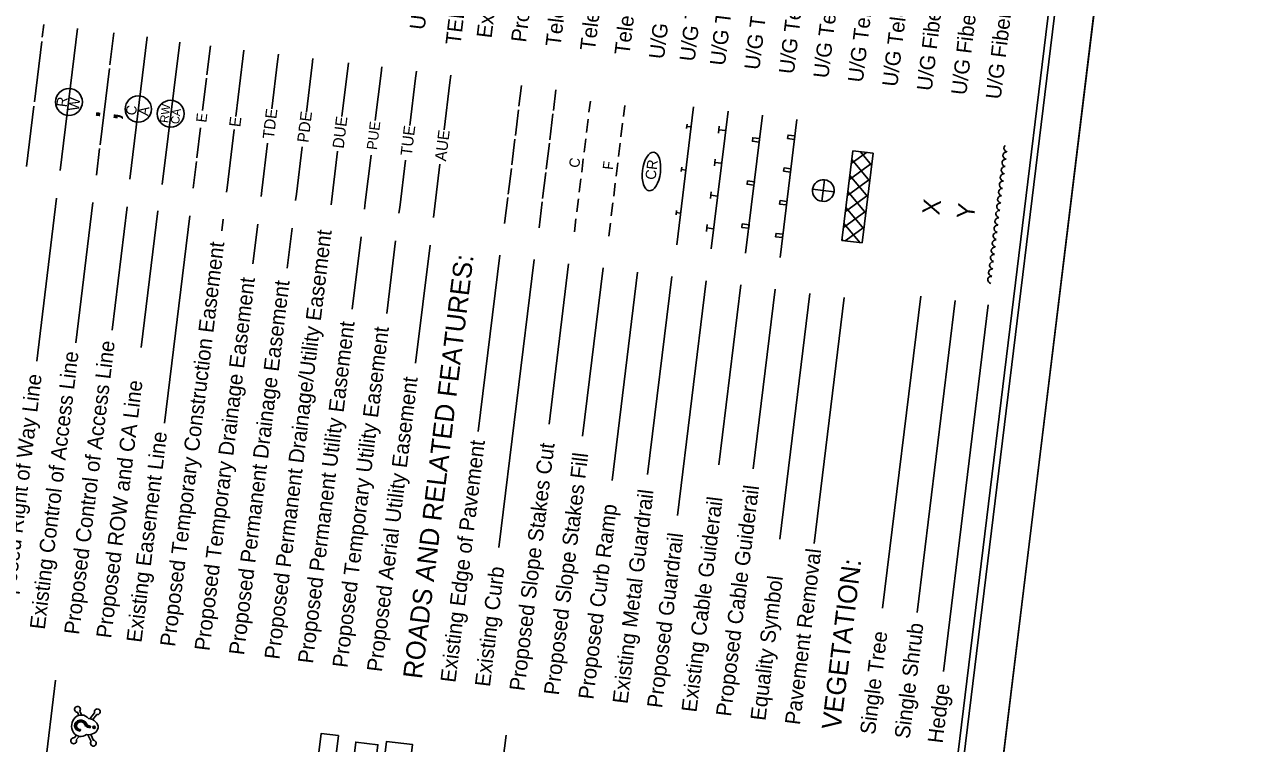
# Model space of a CAD drawing. Extents: x 480781 to 482077, y 490810 to 492615.
# Drawn here: x 481377 to 482077, y 491374 to 491789 of the extents above; entities that cross this region are included whole.
import ezdxf

# ---------------------------------------------------------------- set-up
doc = ezdxf.new("R2010")
doc.units = 0
for name, color, linetype in [('Prop Easement Permanent Drainage Utility', 7, 'Continuous'), ('Prop WCC CELL', 7, 'Continuous'), ('Prop XS SS Elevation Text', 7, 'Continuous'), ('Sheet Cutting Line CELL', 7, 'Continuous'), ('Sheet Plot Border Inside CELL', 7, 'Continuous'), ('Sheet Plot Border Outside CELL', 7, 'Continuous'), ('Sheet Symbology CELL', 7, 'Continuous')]:
    doc.layers.add(name, color=color, linetype=linetype)

msp = doc.modelspace()

# ---------------------------------------------------------------- linework, layer by layer
at = {"layer": 'Prop Easement Permanent Drainage Utility'}
for p, q in [((481559.54, 491735.39), (481563.32, 491766.36)), ((481553.32, 491684.47), (481557.11, 491715.54))]:
    msp.add_line(p, q, dxfattribs=at)
at = {"layer": 'Prop WCC CELL'}
msp.add_ellipse((481737.84, 491703.74), major_axis=(1.36, 11.13), ratio=0.462467, dxfattribs=at)
at = {"layer": 'Prop XS SS Elevation Text'}
for p, q in [((481407.22, 491392.23), (481408.08, 491390.42)), ((481408.63, 491392.89), (481409.69, 491390.65)), ((481414.43, 491388.5), (481417.15, 491391.85)), ((481415.99, 491387.95), (481418.36, 491390.87)), ((481408.84, 491381.28), (481408.96, 491382.26)), ((481411.38, 491384.2), (481411.38, 491384.2)), ((481413.82, 491383.41), (481414.68, 491383.3)), ((481413.83, 491383.55), (481414.7, 491383.44)), ((481413.85, 491383.69), (481414.72, 491383.58)), ((481413.87, 491383.83), (481414.73, 491383.72)), ((481413.88, 491383.97), (481414.75, 491383.86)), ((481413.9, 491384.11), (481414.77, 491384.01)), ((481413.92, 491384.25), (481414.78, 491384.15)), ((481413.94, 491384.39), (481414.8, 491384.29)), ((481414.68, 491383.3), (481414.8, 491384.29)), ((481405.41, 491377.41), (481406.68, 491378.97)), ((481406.62, 491376.43), (481408.19, 491378.35)), ((481413.3, 491379.3), (481415.14, 491375.39)), ((481414.95, 491379.46), (481416.55, 491376.05))]:
    msp.add_line(p, q, dxfattribs=at)
for radius in [0.709, 0.551, 0.391, 0.233, 0.0755]:
    msp.add_circle((481416.88, 491383.57), radius, dxfattribs=at)
for centre, start, end in [((481407.31, 491393.89), 323.23034, 267.1389), ((481418.68, 491392.5), 258.93413, 202.84268), ((481405.1, 491375.79), 78.93413, 22.84268), ((481416.47, 491374.4), 143.23034, 87.1389)]:
    msp.add_arc(centre, 1.66, start, end, dxfattribs=at)
for centre, major_axis, ratio, start_param, end_param in [((481409.43, 491384.44), (0.75, 6.18), 0.885014, 5.564242, 10.143721), ((481412.97, 491384.01), (6.18, -0.75), 0.752542, 4.722735, 7.843636), ((481409.23, 491384.47), (-3.54, 0.43), 0.9, 3.567618, 7.853982), ((481409.23, 491384.47), (-3.39, 0.41), 0.9, 3.567618, 7.853982), ((481409.23, 491384.47), (-3.23, 0.39), 0.9, 3.567618, 7.853982), ((481409.23, 491384.47), (-3.07, 0.38), 0.9, 3.567618, 7.853982), ((481409.23, 491384.47), (-2.92, 0.36), 0.9, 3.567618, 7.853982), ((481409.23, 491384.47), (-2.76, 0.34), 0.9, 3.567618, 7.853982), ((481409.23, 491384.47), (-2.61, 0.32), 0.9, 3.567618, 7.853982), ((481409.23, 491384.47), (-2.45, 0.3), 0.9, 3.567618, 7.853982), ((481414.11, 491385.8), (-2.66, 0.32), 0.9, 0.426026, 1.570796), ((481414.11, 491385.8), (-2.5, 0.31), 0.9, 0.426026, 1.570796), ((481414.11, 491385.8), (-2.35, 0.29), 0.9, 0.426026, 1.570796), ((481414.11, 491385.8), (-2.19, 0.27), 0.9, 0.426026, 1.570796), ((481414.11, 491385.8), (-2.03, 0.25), 0.9, 0.426026, 1.570796), ((481414.11, 491385.8), (-1.88, 0.23), 0.9, 0.426026, 1.570796), ((481414.11, 491385.8), (-1.72, 0.21), 0.9, 0.426026, 1.570796), ((481414.11, 491385.8), (-1.56, 0.19), 0.9, 0.426026, 1.570796)]:
    msp.add_ellipse(centre, major_axis=major_axis, ratio=ratio, start_param=start_param, end_param=end_param, dxfattribs=at)
at = {"layer": 'Sheet Cutting Line CELL'}
msp.add_line((481872.48, 490810.45), (482076.64, 492482.02), dxfattribs=at)
at = {"layer": 'Sheet Plot Border Inside CELL'}
msp.add_lwpolyline([(481851.77, 490826.07), (482053.81, 492480.28), (481006.5, 492608.2), (480804.45, 490953.99)], close=True, dxfattribs=at)
at = {"layer": 'Sheet Plot Border Outside CELL'}
msp.add_lwpolyline([(481872.48, 490810.45), (482076.64, 492482.02), (480984.76, 492615.38), (480780.59, 490943.81)], close=True, dxfattribs=at)
at = {"layer": 'Sheet Symbology CELL'}
for p, q in [((481387.03, 491781.08), (481387.94, 491788.52)), ((481397.34, 491704.26), (481407.34, 491786.15)), ((481425.93, 491765.12), (481428.19, 491783.61)), ((481437.48, 491699.36), (481447.48, 491781.25)), ((481382.48, 491743.86), (481386.73, 491778.6)), ((481456.16, 491696.35), (481466.16, 491778.24)), ((481481.85, 491759.45), (481483.88, 491776.07)), ((481502.59, 491768.86), (481503.19, 491773.71)), ((481498.5, 491735.35), (481502.59, 491768.86)), ((481519.2, 491739.87), (481522.54, 491767.16)), ((481522.54, 491767.16), (481523.04, 491771.28)), ((481542.44, 491765.18), (481542.89, 491768.86)), ((481420.3, 491719.05), (481425.69, 491763.14)), ((481539.11, 491737.89), (481542.44, 491765.18)), ((481578.83, 491733.07), (481582.16, 491760.37)), ((481582.16, 491760.37), (481582.61, 491764.01)), ((481601.96, 491757.46), (481602.46, 491761.58)), ((481479.33, 491738.85), (481481.61, 491757.47)), ((481598.62, 491730.17), (481601.96, 491757.46)), ((481618.47, 491727.74), (481621.81, 491755.04)), ((481621.81, 491755.04), (481622.31, 491759.16)), ((481661.54, 491741.31), (481662.99, 491753.22)), ((481681.39, 491738.88), (481682.84, 491750.79)), ((481377.94, 491706.63), (481382.18, 491741.37)), ((481659.48, 491724.43), (481661.29, 491739.32)), ((481702.67, 491744.19), (481701.89, 491737.84)), ((481722.52, 491741.77), (481721.74, 491735.42)), ((481752.42, 491661.55), (481762.12, 491740.96)), ((481781.97, 491738.53), (481772.27, 491659.12)), ((481679.33, 491722.01), (481681.15, 491736.9)), ((481701.42, 491733.97), (481700.46, 491726.18)), ((481721.27, 491731.54), (481720.32, 491723.75)), ((481792.12, 491656.7), (481801.82, 491736.11)), ((481811.97, 491654.27), (481821.67, 491733.68)), ((481476, 491711.56), (481478.12, 491728.93)), ((481493.5, 491694.41), (481497.59, 491727.91)), ((481758.08, 491728.49), (481758.38, 491730.97)), ((481760.71, 491729.43), (481758.23, 491729.73)), ((481776.44, 491725.83), (481776.92, 491729.8)), ((481780.6, 491727.34), (481776.68, 491727.82)), ((481513.44, 491692.72), (481516.78, 491720.01)), ((481533.35, 491690.74), (481536.68, 491718.04)), ((481657.42, 491707.56), (481659.23, 491722.45)), ((481677.27, 491705.13), (481679.09, 491720.02)), ((481700.02, 491722.5), (481699.08, 491714.81)), ((481719.87, 491720.08), (481718.93, 491712.39)), ((481940.81, 491717.05), (481940.93, 491717.99)), ((481940.93, 491717.99), (481941.52, 491718.72)), ((481941.52, 491718.72), (481941.58, 491718.77)), ((481418.19, 491701.72), (481420.06, 491717.07)), ((481573.07, 491685.92), (481576.4, 491713.22)), ((481592.86, 491683.02), (481596.2, 491710.31)), ((481698.63, 491711.14), (481697.68, 491703.4)), ((481774.14, 491706.97), (481774.62, 491710.94)), ((481847.55, 491663.98), (481853.87, 491715.7)), ((481861.76, 491714.73), (481852.97, 491708.3)), ((481863.53, 491698.3), (481853.24, 491710.58)), ((481853.87, 491715.7), (481865.48, 491714.28)), ((481864.65, 491707.48), (481858.24, 491715.16)), ((481865.48, 491714.28), (481859.17, 491662.56)), ((481939.9, 491709.55), (481940.49, 491710.29)), ((481940.3, 491712.83), (481940.41, 491713.77)), ((481940.65, 491711.98), (481940.3, 491712.83)), ((481940.41, 491713.77), (481941.01, 491714.5)), ((481940.49, 491710.29), (481941.2, 491710.75)), ((481941.22, 491711.3), (481940.65, 491711.98)), ((481941.16, 491716.2), (481940.81, 491717.05)), ((481941.01, 491714.5), (481941.72, 491714.97)), ((481941.74, 491715.52), (481941.16, 491716.2)), ((481941.2, 491710.75), (481942.07, 491710.85)), ((481942.13, 491710.89), (481941.22, 491711.3)), ((481941.72, 491714.97), (481942.59, 491715.07)), ((481942.64, 491715.11), (481941.74, 491715.52)), ((481473.87, 491694.17), (481475.76, 491709.57)), ((481612.71, 491680.59), (481616.05, 491707.89)), ((481655.35, 491690.68), (481657.17, 491705.57)), ((481718.48, 491708.71), (481717.53, 491700.97)), ((481755.04, 491703.68), (481755.35, 491706.16)), ((481757.68, 491704.61), (481755.2, 491704.92)), ((481778.3, 491708.48), (481774.38, 491708.96)), ((481864.79, 491708.62), (481851.84, 491699.07)), ((481939.27, 491704.39), (481939.38, 491705.33)), ((481939.62, 491703.54), (481939.27, 491704.39)), ((481939.38, 491705.33), (481939.98, 491706.07)), ((481940.19, 491702.87), (481939.62, 491703.54)), ((481939.78, 491708.61), (481939.9, 491709.55)), ((481940.13, 491707.76), (481939.78, 491708.61)), ((481939.98, 491706.07), (481940.69, 491706.53)), ((481940.71, 491707.09), (481940.13, 491707.76)), ((481940.69, 491706.53), (481941.56, 491706.63)), ((481941.61, 491706.67), (481940.71, 491707.09)), ((481675.21, 491688.26), (481677.03, 491703.15)), ((481697.2, 491699.48), (481696.28, 491691.93)), ((481717.06, 491697.05), (481716.13, 491689.51)), ((481836.84, 491692.77), (481837.6, 491698.97)), ((481863.66, 491699.39), (481850.72, 491689.89)), ((481862.4, 491689.06), (481852.12, 491701.4)), ((481938.24, 491695.95), (481938.35, 491696.9)), ((481938.35, 491696.9), (481938.95, 491697.63)), ((481938.75, 491700.17), (481938.87, 491701.11)), ((481939.1, 491699.32), (481938.75, 491700.17)), ((481938.87, 491701.11), (481939.46, 491701.85)), ((481938.95, 491697.63), (481939.66, 491698.1)), ((481939.67, 491698.65), (481939.1, 491699.32)), ((481939.46, 491701.85), (481940.17, 491702.32)), ((481939.66, 491698.1), (481940.53, 491698.19)), ((481940.58, 491698.24), (481939.67, 491698.65)), ((481940.17, 491702.32), (481941.04, 491702.41)), ((481941.1, 491702.45), (481940.19, 491702.87)), ((481493.18, 491691.82), (481493.5, 491694.41)), ((481513.04, 491689.39), (481513.44, 491692.72)), ((481532.89, 491686.97), (481533.35, 491690.74)), ((481771.83, 491688.11), (481772.32, 491692.08)), ((481775.99, 491689.62), (481772.07, 491690.1)), ((481830.63, 491693.52), (481836.84, 491692.77)), ((481836.08, 491686.56), (481836.84, 491692.77)), ((481836.84, 491692.77), (481843.04, 491692.01)), ((481862.54, 491690.16), (481849.59, 491680.71)), ((481861.27, 491679.83), (481851, 491692.22)), ((481937.32, 491688.46), (481937.92, 491689.19)), ((481937.72, 491691.73), (481937.84, 491692.68)), ((481938.07, 491690.89), (481937.72, 491691.73)), ((481937.84, 491692.68), (481938.43, 491693.41)), ((481937.92, 491689.19), (481938.63, 491689.66)), ((481938.64, 491690.21), (481938.07, 491690.89)), ((481938.59, 491695.1), (481938.24, 491695.95)), ((481938.43, 491693.41), (481939.14, 491693.88)), ((481939.16, 491694.43), (481938.59, 491695.1)), ((481938.63, 491689.66), (481939.5, 491689.75)), ((481939.55, 491689.8), (481938.64, 491690.21)), ((481939.14, 491693.88), (481940.01, 491693.97)), ((481940.07, 491694.02), (481939.16, 491694.43)), ((481395.27, 491688.37), (481383.81, 491594.54)), ((481416.24, 491685.81), (481406.38, 491605.08)), ((481435.92, 491683.4), (481427.23, 491612.28)), ((481572.6, 491682.12), (481573.07, 491685.92)), ((481592.46, 491679.69), (481592.86, 491683.02)), ((481653.29, 491673.81), (481655.11, 491688.7)), ((481673.15, 491671.39), (481674.96, 491686.27)), ((481695.81, 491688.06), (481694.89, 491680.57)), ((481715.66, 491685.64), (481714.75, 491678.14)), ((481860.15, 491670.65), (481849.87, 491682.99)), ((481936.69, 491683.3), (481936.81, 491684.24)), ((481937.04, 491682.45), (481936.69, 491683.3)), ((481936.81, 491684.24), (481937.4, 491684.97)), ((481937.61, 491681.77), (481937.04, 491682.45)), ((481937.21, 491687.52), (481937.32, 491688.46)), ((481937.56, 491686.67), (481937.21, 491687.52)), ((481937.4, 491684.97), (481938.11, 491685.44)), ((481938.13, 491685.99), (481937.56, 491686.67)), ((481938.11, 491685.44), (481938.98, 491685.54)), ((481939.04, 491685.58), (481938.13, 491685.99)), ((481453.53, 491681.15), (481443.91, 491602.37)), ((481471.93, 491678.26), (481457.35, 491558.86)), ((481491.29, 491676.28), (481490.48, 491669.66)), ((481612.31, 491677.27), (481612.71, 491680.59)), ((481693.47, 491668.9), (481694.39, 491676.45)), ((481752.01, 491678.86), (481752.32, 491681.34)), ((481754.65, 491679.8), (481752.17, 491680.1)), ((481861.41, 491680.97), (481848.47, 491671.47)), ((481935.66, 491674.86), (481935.78, 491675.8)), ((481935.78, 491675.8), (481936.37, 491676.54)), ((481936.18, 491679.08), (481936.29, 491680.02)), ((481936.53, 491678.23), (481936.18, 491679.08)), ((481936.29, 491680.02), (481936.88, 491680.75)), ((481936.37, 491676.54), (481937.08, 491677)), ((481937.1, 491677.56), (481936.53, 491678.23)), ((481936.88, 491680.75), (481937.6, 491681.22)), ((481937.08, 491677), (481937.95, 491677.1)), ((481938.01, 491677.14), (481937.1, 491677.56)), ((481937.6, 491681.22), (481938.46, 491681.32)), ((481938.52, 491681.36), (481937.61, 491681.77)), ((481511.09, 491673.48), (481508.29, 491650.5)), ((481530.95, 491671.05), (481528.14, 491648.07)), ((481713.32, 491666.48), (481714.24, 491674.02)), ((481769.53, 491669.25), (481770.01, 491673.22)), ((481773.69, 491670.76), (481769.77, 491671.24)), ((481858.02, 491662.7), (481848.75, 491673.76)), ((481860.29, 491671.74), (481849.34, 491663.76)), ((481935.15, 491670.64), (481935.26, 491671.58)), ((481935.5, 491669.79), (481935.15, 491670.64)), ((481935.26, 491671.58), (481935.85, 491672.32)), ((481935.34, 491668.1), (481936.05, 491668.57)), ((481936.07, 491669.12), (481935.5, 491669.79)), ((481936.01, 491674.01), (481935.66, 491674.86)), ((481935.85, 491672.32), (481936.57, 491672.78)), ((481936.58, 491673.34), (481936.01, 491674.01)), ((481936.05, 491668.57), (481936.92, 491668.66)), ((481936.97, 491668.71), (481936.07, 491669.12)), ((481936.57, 491672.78), (481937.43, 491672.88)), ((481937.49, 491672.92), (481936.58, 491673.34)), ((481570.66, 491666.2), (481565.55, 491624.38)), ((481590.51, 491663.78), (481585.4, 491621.95)), ((481610.37, 491661.35), (481602.07, 491593.4)), ((481859.17, 491662.56), (481847.55, 491663.98)), ((481848.15, 491663.91), (481847.62, 491664.53)), ((481934.12, 491662.2), (481934.23, 491663.15)), ((481934.47, 491661.36), (481934.12, 491662.2)), ((481934.23, 491663.15), (481934.82, 491663.88)), ((481935.04, 491660.68), (481934.47, 491661.36)), ((481934.63, 491666.42), (481934.75, 491667.37)), ((481934.98, 491665.57), (481934.63, 491666.42)), ((481934.75, 491667.37), (481935.34, 491668.1)), ((481934.82, 491663.88), (481935.54, 491664.35)), ((481935.55, 491664.9), (481934.98, 491665.57)), ((481935.54, 491664.35), (481936.4, 491664.44)), ((481936.46, 491664.49), (481935.55, 491664.9)), ((481650.48, 491655.49), (481638.07, 491553.89)), ((481933.08, 491653.77), (481933.2, 491654.71)), ((481933.2, 491654.71), (481933.79, 491655.44)), ((481933.6, 491657.99), (481933.72, 491658.93)), ((481933.95, 491657.14), (481933.6, 491657.99)), ((481933.72, 491658.93), (481934.31, 491659.66)), ((481933.79, 491655.44), (481934.51, 491655.91)), ((481934.52, 491656.46), (481933.95, 491657.14)), ((481934.31, 491659.66), (481935.02, 491660.13)), ((481934.51, 491655.91), (481935.37, 491656.01)), ((481935.43, 491656.05), (481934.52, 491656.46)), ((481935.02, 491660.13), (481935.89, 491660.22)), ((481935.94, 491660.27), (481935.04, 491660.68)), ((481670.33, 491653.06), (481650.06, 491487.14)), ((481690.18, 491650.64), (481678.88, 491558.14)), ((481710.03, 491648.21), (481698.18, 491551.2)), ((481932.57, 491649.55), (481932.68, 491650.49)), ((481932.92, 491648.7), (481932.57, 491649.55)), ((481932.68, 491650.49), (481933.28, 491651.22)), ((481932.76, 491647.01), (481933.47, 491647.47)), ((481933.49, 491648.02), (481932.92, 491648.7)), ((481933.43, 491652.92), (481933.08, 491653.77)), ((481933.28, 491651.22), (481933.99, 491651.69)), ((481934.01, 491652.24), (481933.43, 491652.92)), ((481933.47, 491647.47), (481934.34, 491647.57)), ((481934.4, 491647.61), (481933.49, 491648.02)), ((481933.99, 491651.69), (481934.86, 491651.79)), ((481934.91, 491651.83), (481934.01, 491652.24)), ((481729.89, 491645.79), (481715.22, 491525.75)), ((481749.6, 491643.22), (481735.68, 491529.23)), ((481769.45, 491640.8), (481752.94, 491505.56)), ((481931.54, 491641.11), (481931.65, 491642.05)), ((481931.89, 491640.26), (481931.54, 491641.11)), ((481931.65, 491642.05), (481932.25, 491642.79)), ((481932.46, 491639.59), (481931.89, 491640.26)), ((481932.05, 491645.33), (481932.17, 491646.27)), ((481932.4, 491644.48), (481932.05, 491645.33)), ((481932.17, 491646.27), (481932.76, 491647.01)), ((481932.25, 491642.79), (481932.96, 491643.25)), ((481932.98, 491643.81), (481932.4, 491644.48)), ((481932.96, 491643.25), (481933.83, 491643.35)), ((481933.88, 491643.39), (481932.98, 491643.81)), ((481789.31, 491638.37), (481776.66, 491534.84)), ((481809.16, 491635.95), (481796.51, 491532.42)), ((481829.01, 491633.52), (481811.72, 491491.95)), ((481933.37, 491639.17), (481932.46, 491639.59)), ((481848.86, 491631.1), (481831.57, 491489.53)), ((481892.93, 491631.9), (481870.97, 491452.11)), ((481912.78, 491629.47), (481890.82, 491449.69)), ((481931.87, 491626.87), (481906.08, 491415.75)), ((481385.03, 491331.37), (481394.72, 491410.78)), ((481644.45, 491299.69), (481654.15, 491379.1))]:
    msp.add_line(p, q, dxfattribs=at)
for points in [[(481007.51, 492595.48), (480825.66, 491106.54), (481866.9, 490979.37), (482048.76, 492468.3)], [(481816.3, 491722.71), (481816.55, 491724.7), (481820.52, 491724.21), (481820.28, 491722.23)], [(481799.94, 491720.7), (481800.18, 491722.68), (481796.21, 491723.17), (481795.97, 491721.18)], [(481814, 491703.85), (481814.24, 491705.84), (481818.21, 491705.35), (481817.97, 491703.37)], [(481796.91, 491695.88), (481797.15, 491697.86), (481793.18, 491698.35), (481792.94, 491696.36)], [(481811.7, 491684.99), (481811.94, 491686.98), (481815.91, 491686.49), (481815.67, 491684.51)], [(481793.88, 491671.06), (481794.12, 491673.05), (481790.15, 491673.53), (481789.91, 491671.55)], [(481809.39, 491666.13), (481809.64, 491668.12), (481813.61, 491667.63), (481813.36, 491665.65)], [(481550.94, 491324.19), (481557.6, 491378.79), (481547.68, 491380), (481541.01, 491325.41)], [(481561.43, 491324.57), (481567.6, 491375.06), (481580.31, 491373.51), (481574.14, 491323.02)], [(481593.58, 491318.98), (481600.25, 491373.58), (481585.36, 491375.4), (481583.64, 491361.34), (481591.09, 491360.43), (481587.85, 491333.95), (481580.41, 491334.86), (481578.69, 491320.8)]]:
    msp.add_lwpolyline(points, close=True, dxfattribs=at)
for centre, radius in [((481402.38, 491743.8), 7.75), ((481442.3, 491739.72), 7.58), ((481460.98, 491737.05), 7.72)]:
    msp.add_circle(centre, radius, dxfattribs=at)
for start, end in [(83.0309, 173.03544), (353.0309, 83.03544), (173.0309, 263.03544), (263.0309, 353.03544)]:
    msp.add_arc((481836.84, 491692.77), 6.25, start, end, dxfattribs=at)

# ---------------------------------------------------------------- texts
at = {"layer": 'Prop Easement Permanent Drainage Utility'}
msp.add_text('DUE', height=6.55, rotation=83.03651, dxfattribs=at).set_placement((481560.58, 491716.72))
at = {"layer": 'Prop WCC CELL'}
msp.add_text('CR', height=6, rotation=83.03651, dxfattribs=at).set_placement((481740.2, 491698.71))
at = {"layer": 'Sheet Symbology CELL'}
for s, height, p in [('U/G Telephone Test Hole (SUE - LOS A)*', 8.75, (481762.68, 491766.83)), ('U/G Telephone Conduit (SUE - LOS B)*', 8.75, (481839.69, 491757.15)), ('U/G Telephone Cable (SUE - LOS B)*', 8.75, (481780.13, 491764.42)), ('U/G Telephone Cable (SUE - LOS C)*', 8.75, (481799.98, 491761.99)), ('U/G Telephone Cable (SUE - LOS D)*', 8.75, (481819.84, 491759.57)), ('U/G Telephone Conduit (SUE - LOS C)*', 8.75, (481859.54, 491754.72)), ('U/G Telephone Conduit (SUE - LOS D)*', 8.75, (481879.39, 491752.3)), ('U/G Power Line (SUE - LOS D)*', 8.75, (481607.19, 491785.03)), ('U/G Fiber Optics Cable (SUE - LOS B)*', 8.75, (481899.25, 491749.87)), ('U/G Fiber Optics Cable (SUE - LOS C)*', 8.75, (481919.1, 491747.45)), ('U/G Fiber Optics Cable (SUE - LOS D)*', 8.75, (481938.95, 491745.02)), ('U/G Telephone Cable Hand Hole', 8.75, (481745.03, 491768.16)), ('Proposed Telephone Pole', 8.75, (481665.62, 491777.84)), ('Existing Telephone Pole', 8.75, (481645.76, 491780.27)), ('Telephone Manhole', 8.75, (481685.47, 491775.42)), ('Telephone Cell Tower', 8.75, (481725.18, 491770.58)), ('Telephone Pedestal', 8.75, (481705.32, 491772.99)), ('TELEPHONE:', 8.75, (481627.87, 491776.35)), ('R', 6.07, (481401.07, 491740.6)), ('W', 6.07, (481408, 491738.35)), ('C', 5.94, (481440.93, 491735.83)), ('A', 5.94, (481448.08, 491735.55)), ('RW', 4.838, (481459.53, 491731.51)), ('CA', 4.838, (481465.78, 491730.82)), ('TDE', 6.55, (481520.37, 491722.19)), ('PDE', 6.55, (481540.26, 491720.12)), (';', 16.5, (481430.17, 491732.28)), ('E', 6, (481481.49, 491731.74)), ('E', 6.55, (481501.06, 491729.1)), ('PUE', 6, (481579.76, 491715.94)), ('TUE', 6.55, (481599.78, 491712.47)), ('AUE', 6.55, (481619.56, 491709.4)), ('C', 5.93, (481696.21, 491705.64)), ('F', 5.93, (481715.58, 491704.48)), ('X', 10, (481903.64, 491678.34)), ('Y', 10, (481923.49, 491675.91)), ('Proposed Permanent Drainage/Utility Easement', 8.75, (481523.58, 491422.36)), ('Proposed Temporary Construction Easement', 8.75, (481463.45, 491429.71)), ('ROADS AND RELATED FEATURES:', 11, (481605.67, 491411.07)), ('Proposed Temporary Drainage Easement', 8.75, (481483.3, 491427.28)), ('Proposed Permanent Drainage Easement', 8.75, (481503.16, 491424.86)), ('Proposed Permanent Utility Easement', 8.75, (481542.87, 491420.01)), ('Proposed Temporary Utility Easement', 8.75, (481562.72, 491417.58)), ('Proposed Control of Access Line', 8.75, (481408.22, 491436.64)), ('Existing Control of Access Line', 8.75, (481388.45, 491439.61)), ('Proposed Right of Way Line', 8.75, (481369.13, 491441.97)), ('Proposed Aerial Utility Easement', 8.75, (481582.57, 491415.16)), ('Proposed ROW and CA Line', 8.75, (481426.71, 491434.56)), ('Existing Easement Line', 8.75, (481444.14, 491432.07)), ('Existing Edge of Pavement', 8.75, (481624.96, 491409.01)), ('Proposed Slope Stakes Cut', 8.75, (481664.66, 491404.16)), ('Proposed Slope Stakes Fill', 8.75, (481684.51, 491401.74)), ('Proposed Cable Guiderail', 8.75, (481783.63, 491389.49)), ('Existing Metal Guardrail', 8.75, (481724.08, 491396.75)), ('Existing Cable Guiderail', 8.75, (481763.77, 491391.91)), ('Proposed Curb Ramp', 8.75, (481704.37, 491399.31)), ('Proposed Guardrail', 8.75, (481743.92, 491394.34)), ('Pavement Removal', 8.75, (481823.33, 491384.64)), ('VEGETATION:', 11, (481846.81, 491381.76)), ('Existing Curb', 8.75, (481644.81, 491406.59)), ('Equality Symbol', 8.75, (481803.48, 491387.06)), ('Single Tree', 8.75, (481866.61, 491379.06)), ('Single Shrub', 8.75, (481886.46, 491376.64)), ('Hedge', 8.75, (481905.54, 491374.04))]:
    msp.add_text(s, height=height, rotation=83.03651, dxfattribs=at).set_placement(p)

doc.saveas('drawing.dxf')
